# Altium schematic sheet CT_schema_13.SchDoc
size 741 x 377 mm
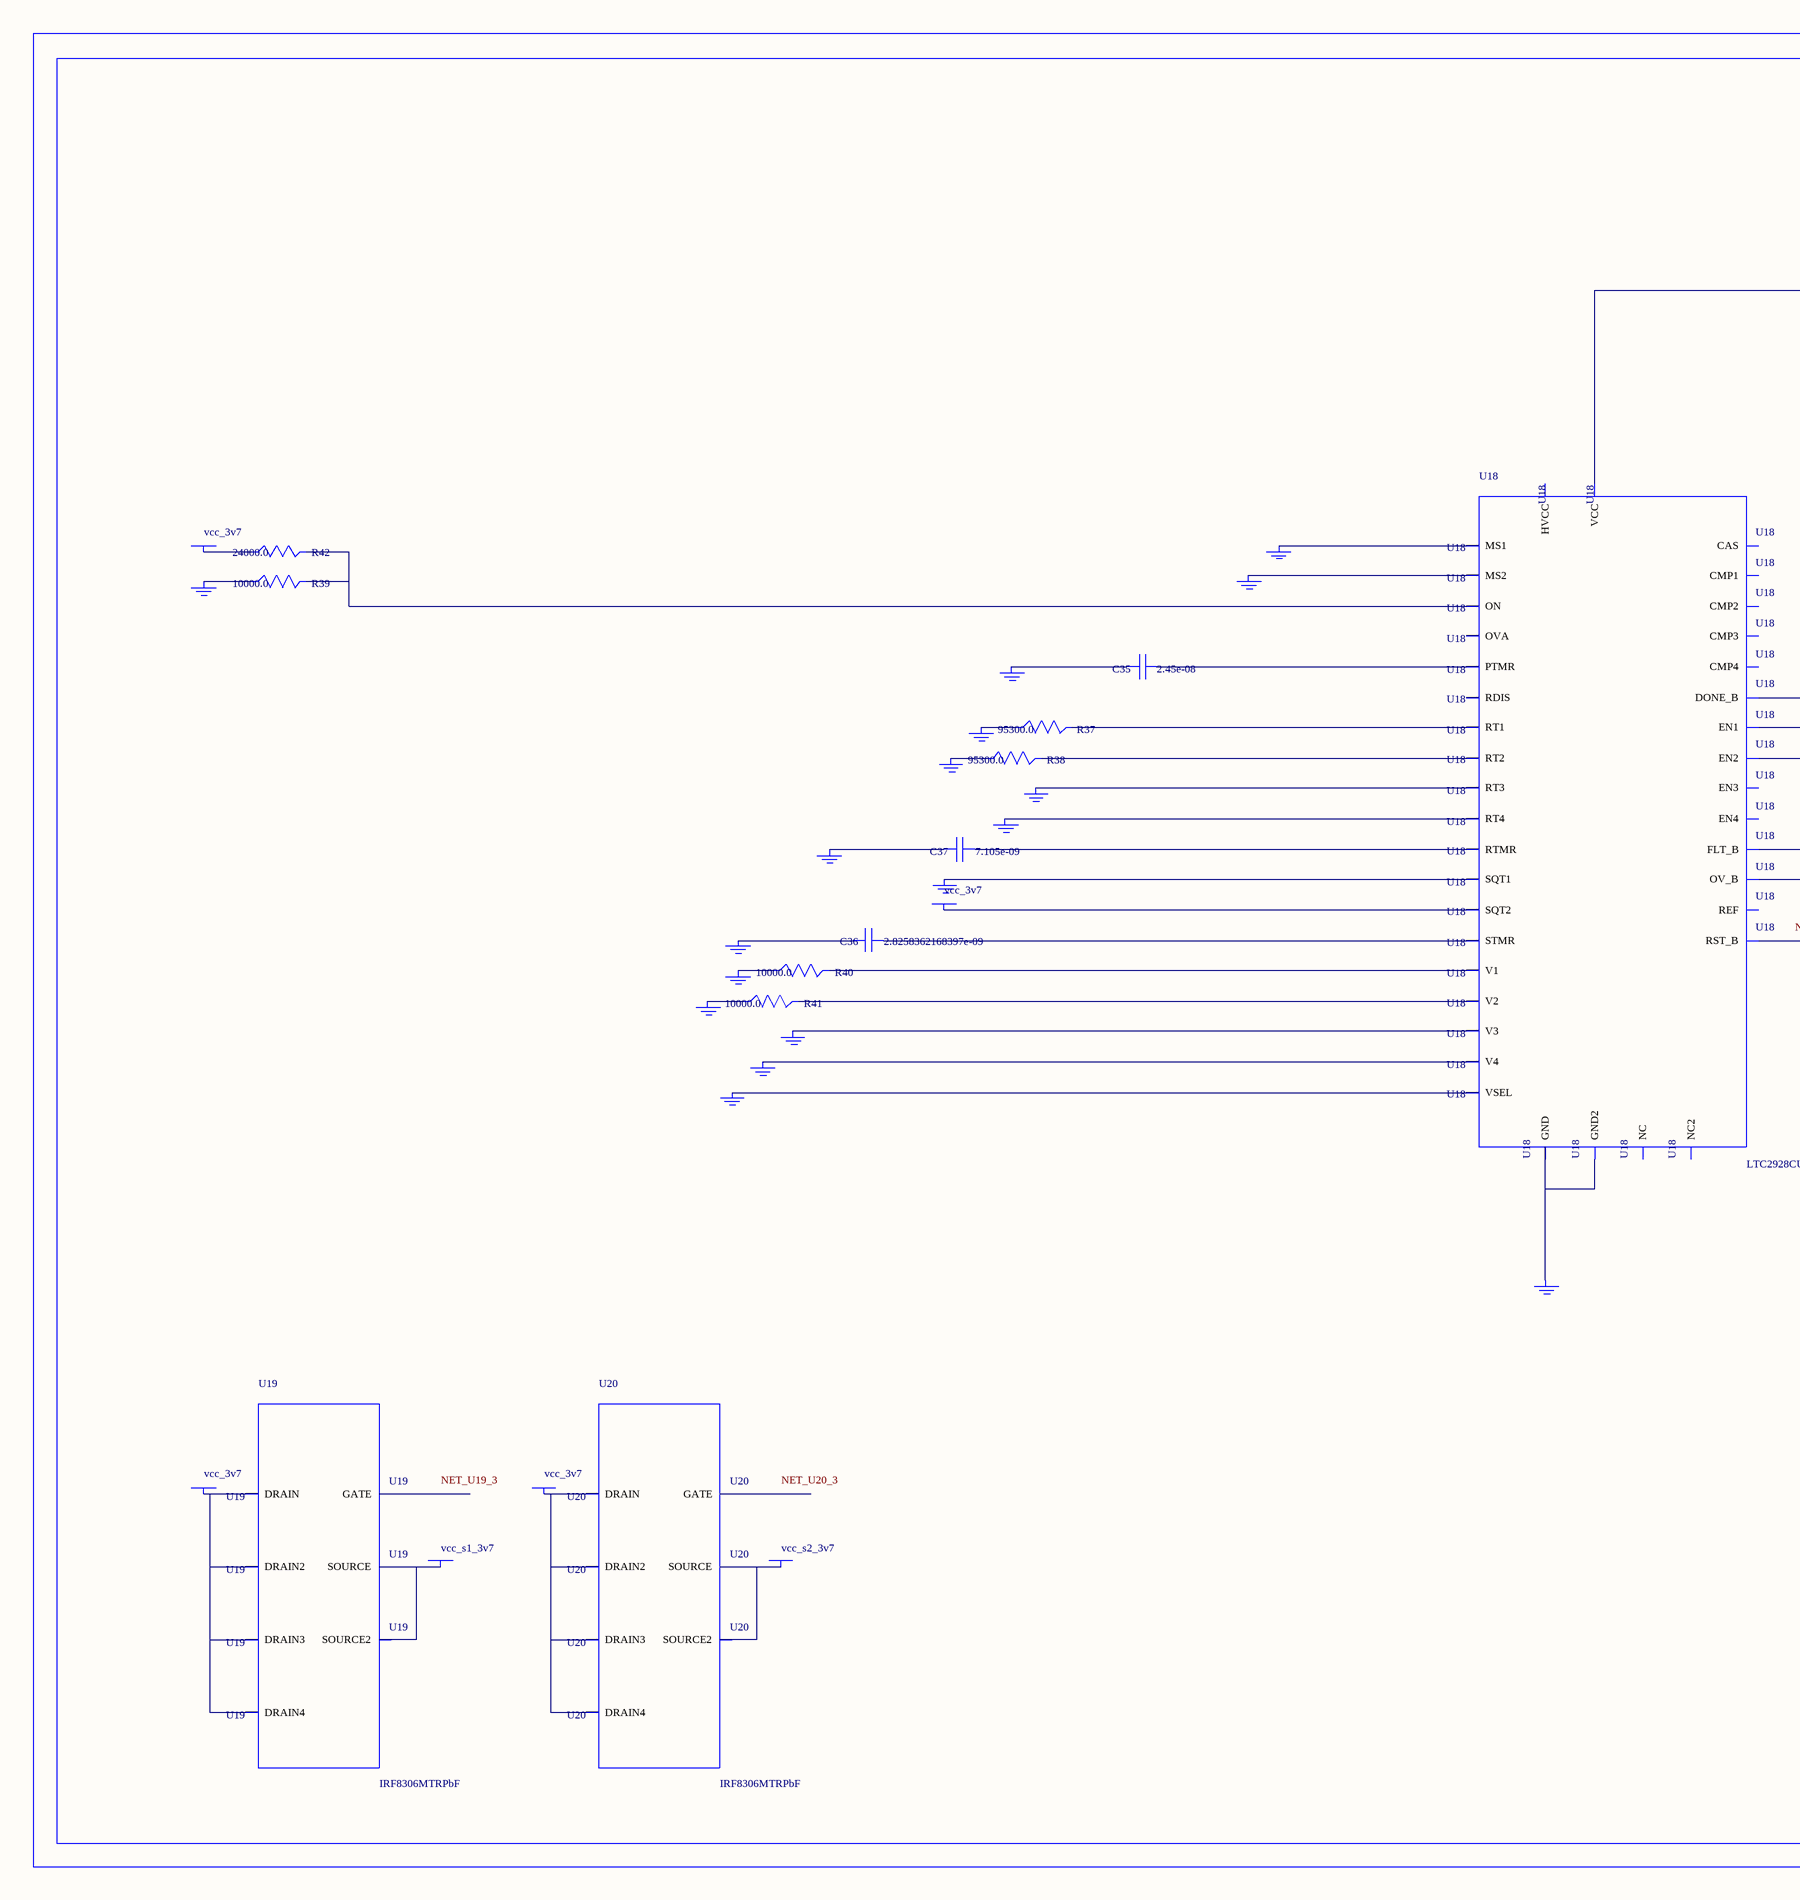
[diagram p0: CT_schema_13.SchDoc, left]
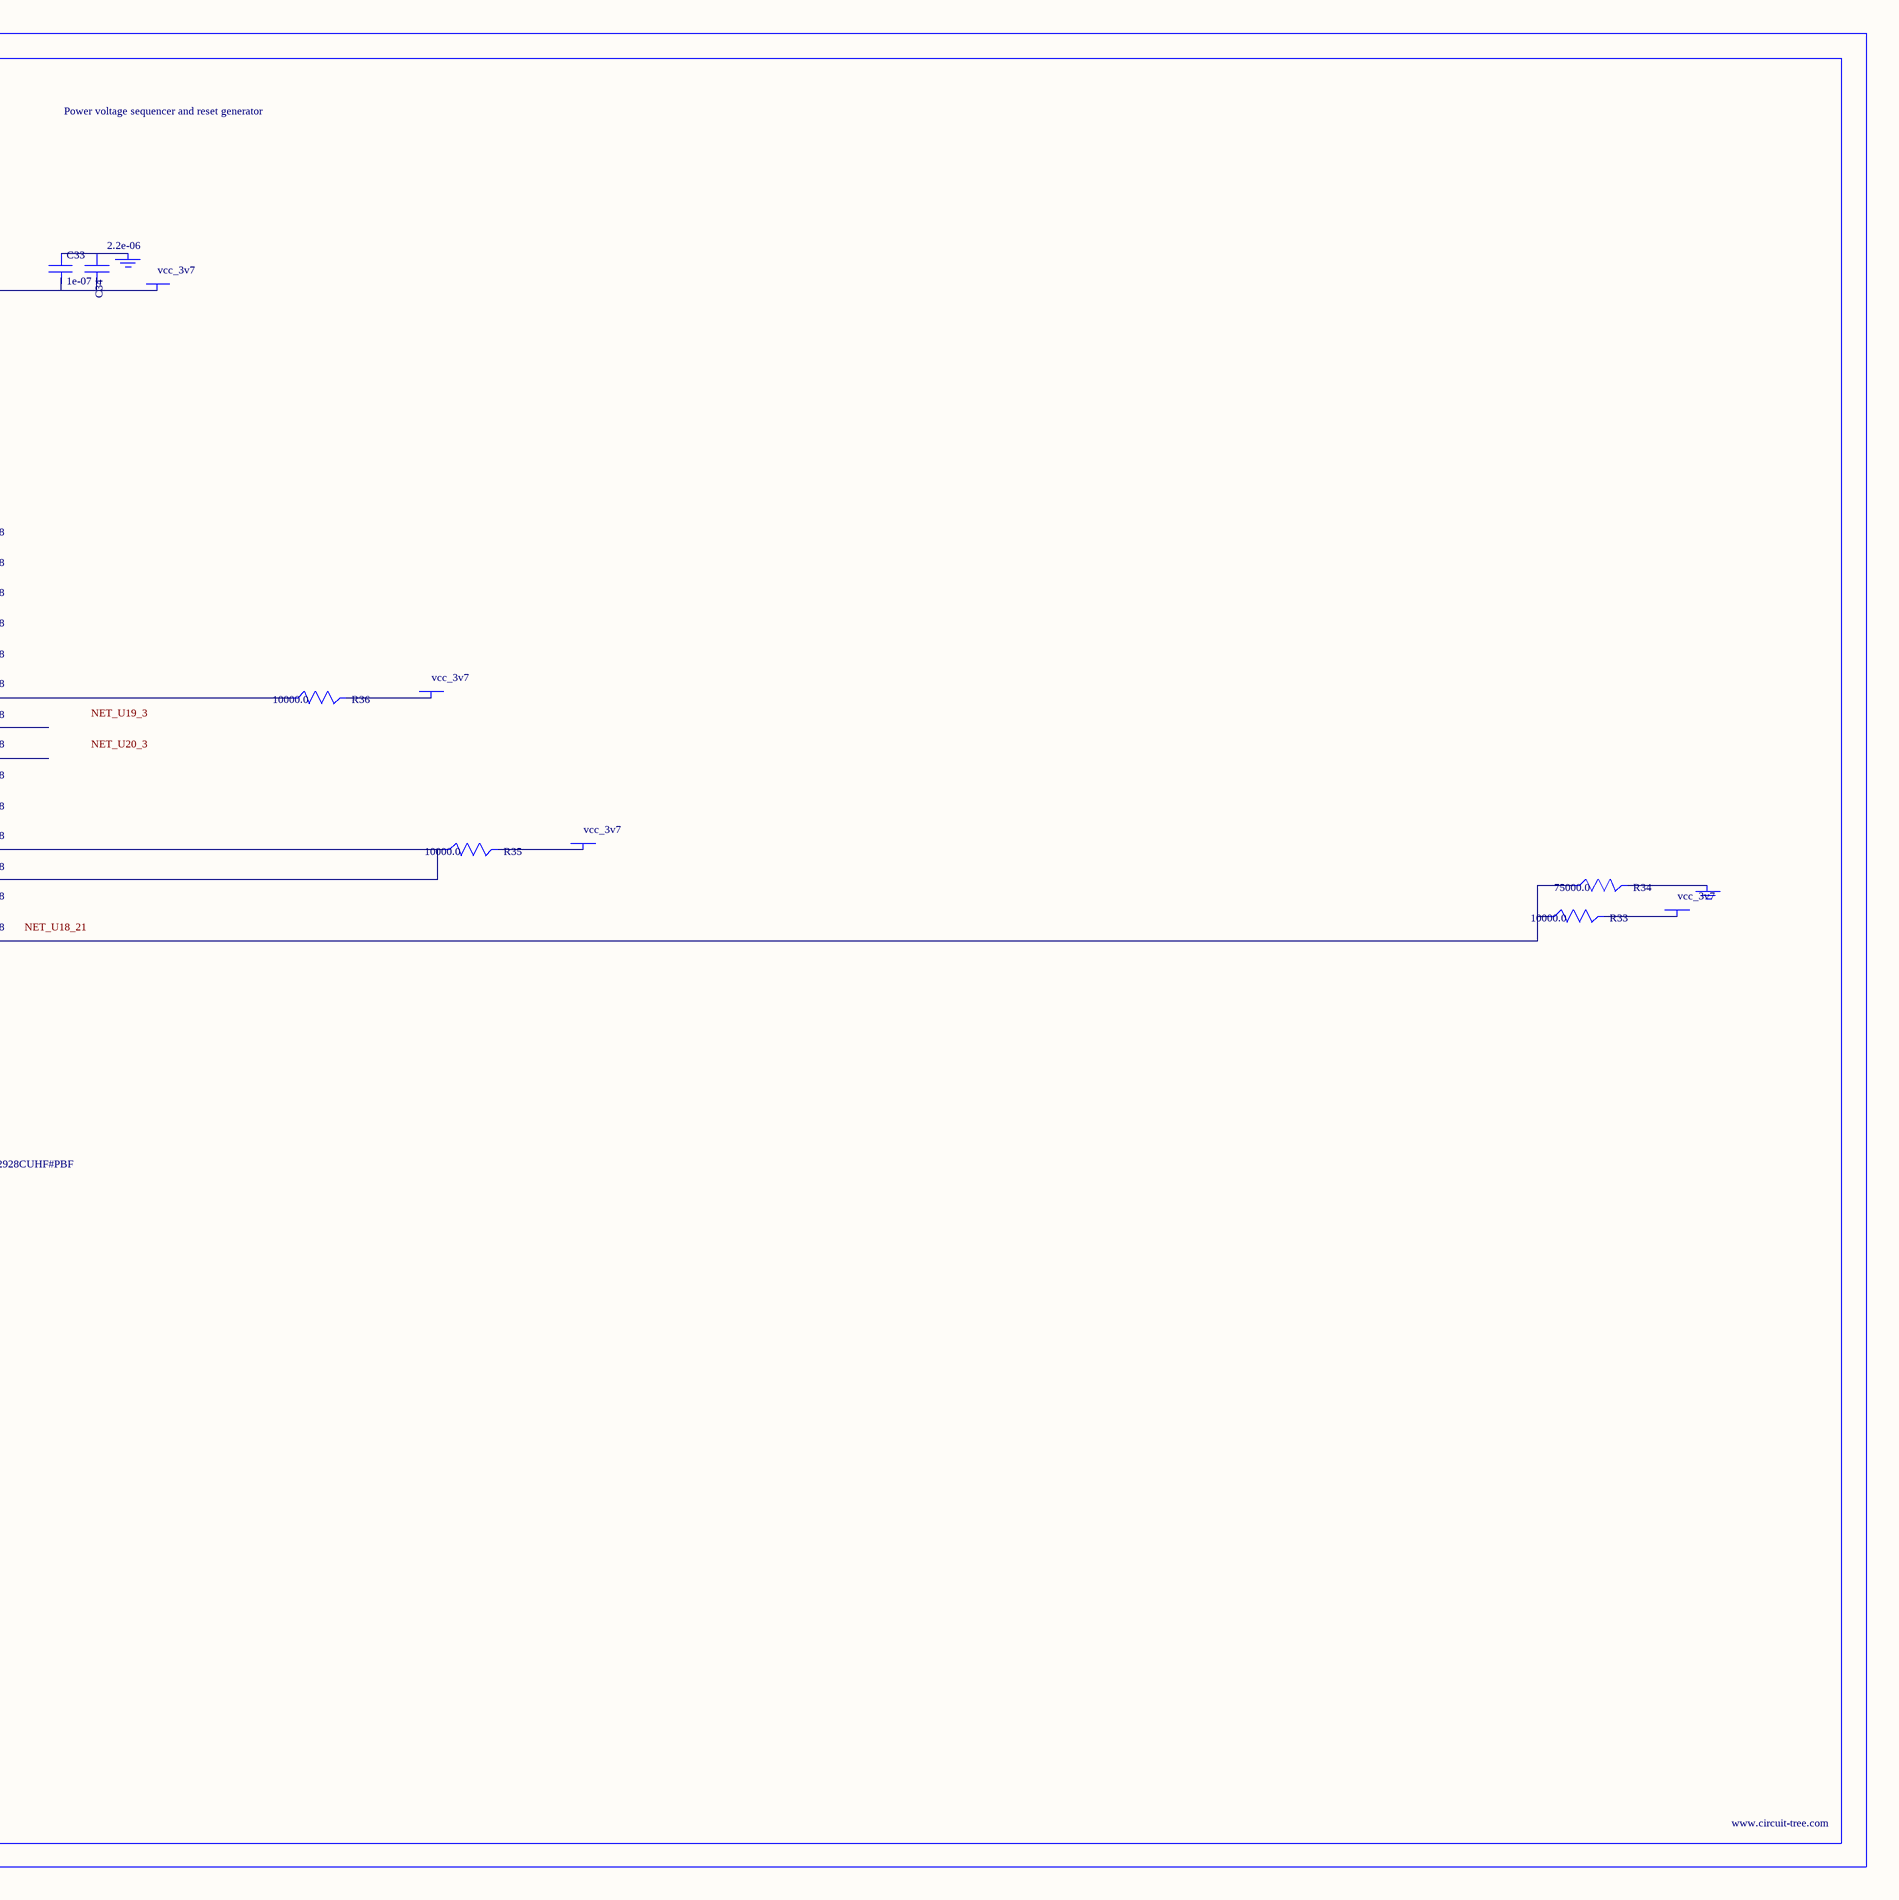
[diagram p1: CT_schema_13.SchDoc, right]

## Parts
BORDER12  (no value)
C33  1e-07  [C0402]
C34  2.2e-06  [C0603]
C35  2.45e-08  [R0603]
C36  2.8258362168397e-09  [R0603]
C37  7.105e-09  [R0603]
GND_INSTANCE_12_0  (no value)
GND_INSTANCE_12_1  (no value)
GND_INSTANCE_12_2  (no value)
GND_INSTANCE_12_3  (no value)
GND_INSTANCE_12_4  (no value)
GND_INSTANCE_12_5  (no value)
GND_INSTANCE_12_6  (no value)
GND_INSTANCE_12_7  (no value)
GND_INSTANCE_12_8  (no value)
GND_INSTANCE_12_9  (no value)
GND_INSTANCE_12_10  (no value)
GND_INSTANCE_12_11  (no value)
GND_INSTANCE_12_12  (no value)
GND_INSTANCE_12_13  (no value)
GND_INSTANCE_12_14  (no value)
GND_INSTANCE_12_15  (no value)
GND_INSTANCE_12_16  (no value)
GND_INSTANCE_12_17  (no value)
GND_INSTANCE_12_18  (no value)
POWER_INSTANCE_12_0  vcc_3v7
POWER_INSTANCE_12_1  vcc_3v7
POWER_INSTANCE_12_2  vcc_3v7
POWER_INSTANCE_12_3  vcc_3v7
POWER_INSTANCE_12_4  vcc_3v7
POWER_INSTANCE_12_5  vcc_3v7
POWER_INSTANCE_12_6  vcc_3v7
POWER_INSTANCE_12_7  vcc_s1_3v7
POWER_INSTANCE_12_8  vcc_3v7
POWER_INSTANCE_12_9  vcc_s2_3v7
R33  10000.0  [R0603]
R34  75000.0  [R0603]
R35  10000.0  [R0603]
R36  10000.0  [R0603]
R37  95300.0  [R0603]
R38  95300.0  [R0603]
R39  10000.0  [R0603]
R40  10000.0  [R0603]
R41  10000.0  [R0603]
R42  24000.0  [R0603]
U18  LTC2928CUHF#PBF  [QFN-38_UHF]
U19  IRF8306MTRPbF  [IRF8306MTRPBF]
U20  IRF8306MTRPbF  [IRF8306MTRPBF]

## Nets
NetC33_1: C33.1 C34.1 GND_INSTANCE_12_10.0(GND)
NetC33_2: C33.2 C34.2 POWER_INSTANCE_12_5.0(PWR) U18.22(VCC)
NetC35_1: C35.1 U18.27(PTMR)
NetC35_2: C35.2 GND_INSTANCE_12_13.0(GND)
NetC36_1: C36.1 U18.26(STMR)
NetC36_2: C36.2 GND_INSTANCE_12_12.0(GND)
NetC37_1: C37.1 U18.28(RTMR)
NetC37_2: C37.2 GND_INSTANCE_12_14.0(GND)
NetGND_INSTANCE_12_0_0: GND_INSTANCE_12_0.0(GND) R40.1
NetGND_INSTANCE_12_1_0: GND_INSTANCE_12_1.0(GND) R37.1
NetGND_INSTANCE_12_2_0: GND_INSTANCE_12_2.0(GND) R38.1
NetGND_INSTANCE_12_3_0: GND_INSTANCE_12_3.0(GND) U18.8(RT3)
NetGND_INSTANCE_12_4_0: GND_INSTANCE_12_4.0(GND) U18.9(RT4)
NetGND_INSTANCE_12_5_0: GND_INSTANCE_12_5.0(GND) U18.10(SQT1)
NetGND_INSTANCE_12_6_0: GND_INSTANCE_12_6.0(GND) U18.12(MS1)
NetGND_INSTANCE_12_7_0: GND_INSTANCE_12_7.0(GND) U18.13(MS2)
NetGND_INSTANCE_12_8_0: GND_INSTANCE_12_8.0(GND) R39.1
NetGND_INSTANCE_12_9_0: GND_INSTANCE_12_9.0(GND) R34.2
NetGND_INSTANCE_12_11_0: GND_INSTANCE_12_11.0(GND) U18.25(VSEL)
NetGND_INSTANCE_12_15_0: GND_INSTANCE_12_15.0(GND) U18.30(V4)
NetGND_INSTANCE_12_16_0: GND_INSTANCE_12_16.0(GND) U18.32(V3)
NetGND_INSTANCE_12_17_0: GND_INSTANCE_12_17.0(GND) R41.1
NetGND_INSTANCE_12_18_0: GND_INSTANCE_12_18.0(GND) U18.24(GND) U18.39(GND2)
NetPOWER_INSTANCE_12_0_0: POWER_INSTANCE_12_0.0(PWR) U18.11(SQT2)
NetPOWER_INSTANCE_12_1_0: POWER_INSTANCE_12_1.0(PWR) R42.1
NetPOWER_INSTANCE_12_2_0: POWER_INSTANCE_12_2.0(PWR) R36.2
NetPOWER_INSTANCE_12_3_0: POWER_INSTANCE_12_3.0(PWR) R35.2
NetPOWER_INSTANCE_12_4_0: POWER_INSTANCE_12_4.0(PWR) R33.2
NetPOWER_INSTANCE_12_6_0: POWER_INSTANCE_12_6.0(PWR) U19.1(DRAIN) U19.2(DRAIN2) U19.6(DRAIN3) U19.7(DRAIN4)
NetPOWER_INSTANCE_12_7_0: POWER_INSTANCE_12_7.0(PWR) U19.4(SOURCE) U19.5(SOURCE2)
NetPOWER_INSTANCE_12_8_0: POWER_INSTANCE_12_8.0(PWR) U20.1(DRAIN) U20.2(DRAIN2) U20.6(DRAIN3) U20.7(DRAIN4)
NetPOWER_INSTANCE_12_9_0: POWER_INSTANCE_12_9.0(PWR) U20.4(SOURCE) U20.5(SOURCE2)
NetR33_1: R33.1 R34.1 U18.21(RST_B)
NetR35_1: R35.1 U18.19(FLT_B) U18.20(OV_B)
NetR36_1: R36.1 U18.18(DONE_B)
NetR37_2: R37.2 U18.6(RT1)
NetR38_2: R38.2 U18.7(RT2)
NetR39_2: R39.2 R42.2 U18.16(ON)
NetR40_2: R40.2 U18.3(V1)
NetR41_2: R41.2 U18.38(V2)

Not connected (* = marked no-connect by the designer): U18 1(OVA) 2(EN1) 4(NC) 5(REF) 14(RDIS) 15(CAS) 17(NC2) 23(HVCC) 29(EN4) 31(EN3) 33(CMP3) 34(CMP4) 35(CMP1) 36(CMP2) 37(EN2); U19 3(GATE); U20 3(GATE)

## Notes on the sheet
- Labels drawn without touching a wire or pin: NET_U18_21, NET_U19_3, NET_U20_3

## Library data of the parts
BORDER12 = BORDER_PAGE12
C33 = C0402C104K3RACTU
C34 = GRM188R61H225KE1115D
C35 = C35
C36 = C36
C37 = C37
GND_INSTANCE_12_0-GND_INSTANCE_12_18 = GND
POWER_INSTANCE_12_0-POWER_INSTANCE_12_9 = PWR
R33 R35 R36 R39-R41 = RC0603JR-0710KL
R34 = RC0603JR-0775KL
R37 R38 = RC0603FR-0795K3L
R42 = RC0603JR-0724KL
